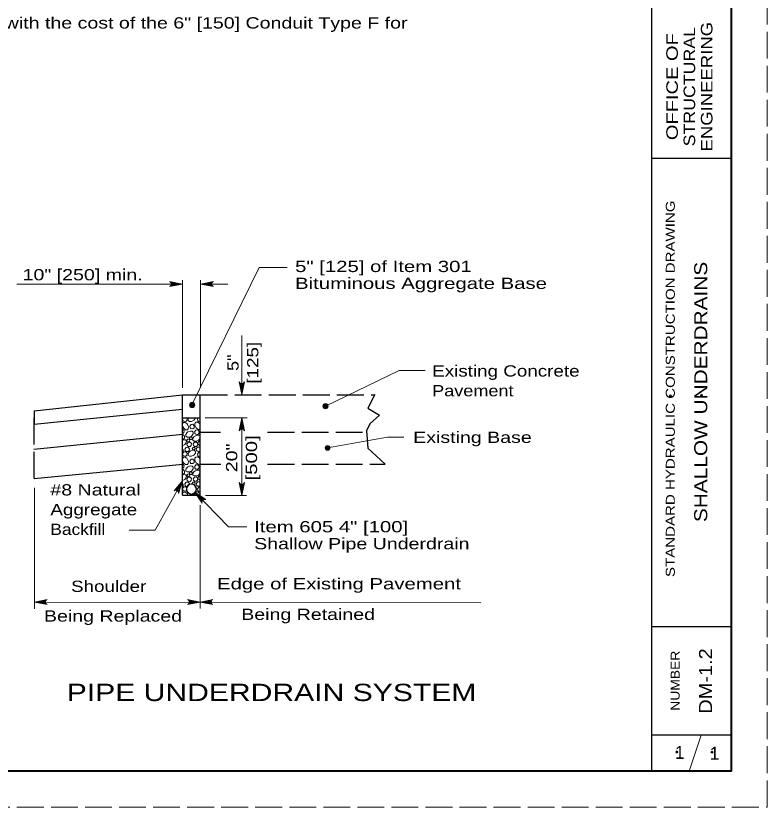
# Model space of a CAD drawing. Extents: x 743.9 to 777.9, y 1051 to 1073.
# Drawn here: x 767.45 to 777.86, y 1051.02 to 1062 of the extents above; entities that cross this region are included whole.
import ezdxf
from ezdxf.enums import TextEntityAlignment as Align

# ---------------------------------------------------------------- set-up
doc = ezdxf.new("R2010")
doc.units = 0
doc.header["$LTSCALE"] = 0.062
doc.header["$PDMODE"] = 32
doc.header["$PDSIZE"] = 0.031
doc.linetypes.add('LONG_DASHED', pattern=[7.5, 6, -1.5])
doc.layers.add('1', color=7, linetype='Continuous', lineweight=13)

msp = doc.modelspace()

# ---------------------------------------------------------------- hatches: boundary and pattern name
at = {"layer": '1'}
for points in [[(769.92886, 1056.59658, 1), (769.85571, 1056.59658, 1)], [(771.77651, 1056.58065, 1), (771.70336, 1056.58065, 1)], [(771.80127, 1056.00261, 1), (771.73603, 1056.00261, 1)]]:
    msp.add_hatch(color=256, dxfattribs=at).paths.add_polyline_path(points)

# ---------------------------------------------------------------- linework, layer by layer
at = {"layer": '1', "lineweight": 25}
for p, q in [((776.26317, 1051.51808), (776.26317, 1072.51808)), ((777.36317, 1072.51808), (777.36317, 1051.51808)), ((777.36317, 1060.01808), (776.26317, 1060.01808)), ((767.70358, 1056.51633), (769.75942, 1056.74008)), ((769.75942, 1055.3475), (769.75942, 1056.74008)), ((769.75942, 1056.74008), (770.00417, 1056.74008)), ((770.00417, 1055.34517), (770.00417, 1056.74008)), ((767.69958, 1056.33075), (769.7575, 1056.53842)), ((767.70358, 1056.51633), (767.70358, 1056.33075)), ((769.75942, 1056.41667), (770.00525, 1056.41667)), ((767.69542, 1055.98542), (769.76075, 1056.19383)), ((767.70358, 1055.57525), (769.76275, 1055.77817)), ((769.75942, 1055.3475), (770.00417, 1055.34517)), ((777.36317, 1053.51808), (776.26317, 1053.51808)), ((777.36317, 1052.01808), (776.26317, 1052.01808))]:
    msp.add_line(p, q, dxfattribs=at)
at = {"layer": '1'}
for p, q in [((769.88458, 1056.58892), (770.8195, 1058.50383)), ((770.8195, 1058.50383), (771.20708, 1058.50383)), ((767.4595, 1058.27442), (769.75608, 1058.27442)), ((769.59392, 1058.24958), (769.75608, 1058.27442)), ((769.59583, 1058.29683), (769.75608, 1058.27442)), ((769.60008, 1058.26), (769.75608, 1058.27442)), ((769.60125, 1058.28575), (769.75608, 1058.27442)), ((769.60292, 1058.27442), (769.75608, 1058.27442)), ((769.75667, 1056.83492), (769.75667, 1058.32867)), ((770.00917, 1056.83492), (770.00917, 1058.32867)), ((770.17008, 1058.29683), (770.00983, 1058.27442)), ((770.16467, 1058.28575), (770.00983, 1058.27442)), ((770.00983, 1058.27442), (770.38867, 1058.27442)), ((770.163, 1058.27442), (770.00983, 1058.27442)), ((770.16583, 1058.26), (770.00983, 1058.27442)), ((770.172, 1058.24958), (770.00983, 1058.27442)), ((770.581, 1056.74008), (770.581, 1057.56217)), ((770.60583, 1056.90242), (770.581, 1056.74033)), ((770.55858, 1056.90058), (770.581, 1056.74033)), ((770.56975, 1056.89517), (770.581, 1056.74033)), ((770.59542, 1056.89633), (770.581, 1056.74033)), ((770.581, 1056.8935), (770.581, 1056.74033)), ((769.75942, 1056.40458), (769.76792, 1056.41667)), ((769.96542, 1056.39983), (769.97717, 1056.41667)), ((770.072, 1056.41667), (770.65317, 1056.41667)), ((770.55617, 1056.2545), (770.581, 1056.41667)), ((770.56658, 1056.26067), (770.581, 1056.41667)), ((770.581, 1056.2635), (770.581, 1056.41667)), ((770.59233, 1056.26183), (770.581, 1056.41667)), ((770.60342, 1056.25642), (770.581, 1056.41667)), ((770.00058, 1056.33142), (770.00242, 1056.327)), ((769.99625, 1056.22383), (770.0025, 1056.23242)), ((771.76867, 1056.00258), (772.59792, 1056.15175)), ((772.59792, 1056.15175), (772.82492, 1056.15175)), ((770.00058, 1055.848), (770.00325, 1055.84117)), ((769.99625, 1055.74042), (770.0035, 1055.75058)), ((769.75942, 1055.54325), (769.3795, 1054.86108)), ((769.66233, 1055.41383), (769.75942, 1055.54325)), ((769.67467, 1055.41325), (769.75942, 1055.54325)), ((769.68533, 1055.40925), (769.75942, 1055.54325)), ((769.69658, 1055.39975), (769.75942, 1055.54325)), ((769.70267, 1055.38933), (769.75942, 1055.54325)), ((770.55858, 1055.50342), (770.581, 1055.34317)), ((770.56967, 1055.498), (770.581, 1055.34317)), ((770.60575, 1055.50533), (770.581, 1055.34317)), ((770.59533, 1055.49917), (770.581, 1055.34317)), ((770.581, 1055.49633), (770.581, 1055.34317)), ((767.70592, 1055.44558), (767.70592, 1053.7715)), ((770.03817, 1055.27675), (769.93125, 1055.38642)), ((770.0505, 1055.28475), (769.93125, 1055.38642)), ((770.06217, 1055.28758), (769.93125, 1055.38642)), ((770.03125, 1055.26767), (769.93125, 1055.38642)), ((770.02708, 1055.256), (769.93125, 1055.38642)), ((769.82858, 1055.36058), (769.83408, 1055.34675)), ((770.00058, 1055.36475), (770.00417, 1055.3555)), ((770.07858, 1055.34342), (770.64308, 1055.34342)), ((770.0035, 1053.77283), (770.0035, 1055.20825)), ((769.01842, 1054.86108), (769.3795, 1054.86108)), ((767.86617, 1053.88558), (767.70592, 1053.86317)), ((767.86075, 1053.8745), (767.70592, 1053.86317)), ((767.70592, 1053.86317), (773.89367, 1053.85258)), ((767.85908, 1053.86317), (767.70592, 1053.86317)), ((767.86192, 1053.84875), (767.70592, 1053.86317)), ((767.86808, 1053.83842), (767.70592, 1053.86317)), ((769.84133, 1053.83842), (770.0035, 1053.86317)), ((769.84325, 1053.88558), (770.0035, 1053.86317)), ((769.8475, 1053.84875), (770.0035, 1053.86317)), ((769.84867, 1053.8745), (770.0035, 1053.86317)), ((769.85033, 1053.86317), (770.0035, 1053.86317)), ((770.16375, 1053.88558), (770.0035, 1053.86317)), ((770.15833, 1053.8745), (770.0035, 1053.86317)), ((770.15667, 1053.86317), (770.0035, 1053.86317)), ((770.1595, 1053.84875), (770.0035, 1053.86317)), ((770.16567, 1053.83842), (770.0035, 1053.86317)), ((776.77983, 1051.51808), (776.9465, 1052.01808))]:
    msp.add_line(p, q, dxfattribs=at)
at = {"layer": '1', "linetype": 'LONG_DASHED', "lineweight": 25}
for p, q in [((770.01133, 1056.74008), (772.42617, 1056.74008)), ((767.70358, 1055.57525), (767.70358, 1056.51633)), ((770.00808, 1056.22125), (770.28617, 1056.22125)), ((770.93842, 1056.22125), (772.31067, 1056.22125)), ((770.003, 1055.77817), (770.28842, 1055.77817)), ((770.93842, 1055.77817), (772.56642, 1055.77817))]:
    msp.add_line(p, q, dxfattribs=at)
at = {"layer": '1', "linetype": 'LONG_DASHED'}
msp.add_lwpolyline([(743.86317, 1051.01808), (777.86317, 1051.01808), (777.86317, 1073.01808), (743.86317, 1073.01808)], close=True, dxfattribs=at)
at = {"layer": '1', "lineweight": 25}
msp.add_lwpolyline([(777.36317, 1051.51808), (745.86317, 1051.51808), (745.86317, 1072.51808)], dxfattribs=at)
at = {"layer": '1', "lineweight": 40}
msp.add_lwpolyline([(745.86317, 1072.51808), (777.36317, 1072.51808), (777.36317, 1051.51808), (745.86317, 1051.51808)], close=True, dxfattribs=at)
msp.add_lwpolyline([(745.86317, 1072.51808), (777.36317, 1072.51808), (777.36317, 1051.51808), (745.86317, 1051.51808)], close=True, dxfattribs=at)
at = {"layer": '1'}
for points in [[(769.57908, 1058.239), (769.75608, 1058.27442), (769.57908, 1058.30983)], [(770.18683, 1058.239), (770.00983, 1058.27442), (770.18683, 1058.30983)], [(771.73992, 1056.58067), (772.7615, 1057.07483), (773.12267, 1057.07483)], [(770.61642, 1056.91733), (770.581, 1056.74033), (770.54567, 1056.91733)], [(769.81658, 1056.41667), (769.82225, 1056.41075), (769.81958, 1056.3835), (769.80283, 1056.36958), (769.77617, 1056.37158), (769.7635, 1056.38367), (769.75942, 1056.40408)], [(769.75942, 1056.33867), (769.7705, 1056.35417), (769.79492, 1056.35592), (769.81675, 1056.34183), (769.82942, 1056.32583)], [(769.93725, 1056.41667), (769.93708, 1056.413), (769.91617, 1056.38608), (769.88375, 1056.36992), (769.85317, 1056.36933), (769.83592, 1056.38158), (769.83433, 1056.40592), (769.84125, 1056.41667)], [(770.0025, 1056.262), (769.9975, 1056.25675), (769.97392, 1056.25725), (769.947, 1056.27817), (769.93083, 1056.31058), (769.93033, 1056.341), (769.9425, 1056.35825), (769.96683, 1056.36), (769.98867, 1056.34608), (770.00133, 1056.32992)], [(770.00225, 1056.36542), (769.982, 1056.36675), (769.9695, 1056.379), (769.96542, 1056.39983)], [(770.54558, 1056.23967), (770.581, 1056.41667), (770.61633, 1056.23967)], [(770.581, 1055.3495), (770.581, 1055.863), (770.581, 1056.41667)], [(769.82858, 1056.32708), (769.84117, 1056.2955), (769.83867, 1056.26642), (769.8255, 1056.25258), (769.80192, 1056.253), (769.77508, 1056.27408), (769.75942, 1056.30525)], [(769.75942, 1056.26217), (769.76167, 1056.26225), (769.7805, 1056.24283), (769.77767, 1056.21558), (769.76108, 1056.20175), (769.75942, 1056.20175)], [(769.859, 1056.30317), (769.876, 1056.32733), (769.90283, 1056.32892), (769.92175, 1056.30933), (769.919, 1056.28208), (769.90225, 1056.26817), (769.87558, 1056.27017), (769.86308, 1056.28225), (769.85908, 1056.30317)], [(769.92667, 1056.22467), (769.94367, 1056.24875), (769.97067, 1056.25042), (769.9895, 1056.23083), (769.98667, 1056.20367), (769.97008, 1056.18983), (769.94342, 1056.19167), (769.93083, 1056.20383), (769.92675, 1056.22467)], [(769.75942, 1056.18258), (769.76917, 1056.18317), (769.78792, 1056.16367), (769.78517, 1056.13633), (769.76858, 1056.12258), (769.75942, 1056.12308)], [(769.83233, 1056.22258), (769.86392, 1056.23517), (769.89317, 1056.23267), (769.90692, 1056.2195), (769.90642, 1056.196), (769.8855, 1056.169), (769.85308, 1056.15283), (769.82242, 1056.15233), (769.80542, 1056.16458), (769.80367, 1056.18883), (769.81775, 1056.21067), (769.83375, 1056.22333)], [(770.00267, 1056.13683), (769.98383, 1056.11242), (769.95142, 1056.09642), (769.92075, 1056.09583), (769.9035, 1056.108), (769.90192, 1056.13225), (769.91583, 1056.15408), (769.93183, 1056.16683)], [(769.93058, 1056.166), (769.96225, 1056.1785), (769.99125, 1056.17617), (770.00258, 1056.16525)], [(770.0025, 1056.20067), (770.00033, 1056.20283), (769.99633, 1056.22383)], [(769.75942, 1056.1105), (769.76867, 1056.11408), (769.79792, 1056.11158), (769.81158, 1056.09842), (769.81117, 1056.07483), (769.79025, 1056.048), (769.75942, 1056.03258)], [(770.00283, 1056.04008), (769.98867, 1056.04108), (769.97608, 1056.05317), (769.972, 1056.07417), (769.98883, 1056.09817), (770.00283, 1056.099)], [(769.75942, 1055.98458), (769.76558, 1055.97875), (769.76508, 1055.95525), (769.75942, 1055.94808)], [(769.75942, 1055.9215), (769.77633, 1055.94533), (769.80342, 1055.947), (769.82225, 1055.9275), (769.81958, 1055.90017), (769.80283, 1055.88633), (769.77617, 1055.88817), (769.7635, 1055.9005), (769.75942, 1055.92083)], [(769.86308, 1055.95633), (769.89458, 1055.96892), (769.92375, 1055.96633), (769.93758, 1055.95317), (769.93708, 1055.92958), (769.91617, 1055.90275), (769.88375, 1055.88658), (769.85317, 1055.88608), (769.83592, 1055.89825), (769.83433, 1055.92258), (769.84842, 1055.94433), (769.86425, 1055.95717)], [(769.894, 1055.99492), (769.90408, 1056.00933), (769.92033, 1056.01025), (769.93167, 1055.99858), (769.93, 1055.98217), (769.92, 1055.97392), (769.90392, 1055.97508), (769.89658, 1055.98233), (769.89408, 1055.99492)], [(769.94933, 1055.98875), (769.96633, 1056.01275), (769.99342, 1056.01425), (770.00292, 1056.00442)], [(770.003, 1055.96225), (769.99283, 1055.95358), (769.96608, 1055.95558), (769.9535, 1055.96775), (769.94942, 1055.98875)], [(770.00317, 1055.88192), (769.982, 1055.8835), (769.9695, 1055.89575), (769.96542, 1055.91658), (769.98233, 1055.94067), (770.003, 1055.94192)], [(769.75942, 1055.85542), (769.7705, 1055.87092), (769.79492, 1055.87267), (769.81675, 1055.85858), (769.82942, 1055.84258)], [(769.82858, 1055.84383), (769.84117, 1055.81217), (769.83867, 1055.78325), (769.8255, 1055.76933), (769.80192, 1055.76967), (769.77508, 1055.79075), (769.75942, 1055.82192)], [(769.859, 1055.81992), (769.876, 1055.844), (769.90283, 1055.84558), (769.92175, 1055.82608), (769.919, 1055.79875), (769.90225, 1055.78492), (769.87558, 1055.78692), (769.86308, 1055.799), (769.85908, 1055.81992)], [(770.00342, 1055.77967), (769.9975, 1055.7735), (769.97392, 1055.774), (769.947, 1055.79483), (769.93083, 1055.82733), (769.93033, 1055.85792), (769.9425, 1055.875), (769.96683, 1055.87675), (769.98867, 1055.86267), (770.00133, 1055.84667)], [(769.75942, 1055.77892), (769.76167, 1055.779), (769.7805, 1055.75942), (769.77767, 1055.73233), (769.76108, 1055.71842), (769.75942, 1055.7185)], [(769.75942, 1055.69933), (769.76917, 1055.69992), (769.78792, 1055.68042), (769.78517, 1055.65308), (769.76858, 1055.63917), (769.75942, 1055.63992)], [(769.83233, 1055.73933), (769.86392, 1055.75175), (769.89317, 1055.74933), (769.90692, 1055.73625), (769.90642, 1055.71258), (769.8855, 1055.68575), (769.85308, 1055.6695), (769.82242, 1055.669), (769.80542, 1055.68133), (769.80367, 1055.70558), (769.81775, 1055.72725), (769.83375, 1055.74008)], [(769.92667, 1055.74142), (769.94367, 1055.76558), (769.97067, 1055.76708), (769.9895, 1055.74758), (769.98667, 1055.72042), (769.97008, 1055.70642), (769.94342, 1055.70842), (769.93083, 1055.72058), (769.92675, 1055.74142)], [(769.93058, 1055.68275), (769.96225, 1055.69525), (769.99125, 1055.69275), (770.00367, 1055.68108)], [(770.00367, 1055.71658), (770.00033, 1055.71958), (769.99633, 1055.74042)], [(769.75942, 1055.62717), (769.76867, 1055.63075), (769.79792, 1055.62833), (769.81158, 1055.61517), (769.81117, 1055.59158), (769.79025, 1055.56475), (769.75942, 1055.5495)], [(770.00367, 1055.65467), (769.98383, 1055.62917), (769.95142, 1055.613), (769.92075, 1055.61258), (769.9035, 1055.62475), (769.90192, 1055.649), (769.91583, 1055.67075), (769.93183, 1055.68358)], [(770.00392, 1055.55675), (769.98867, 1055.55783), (769.97608, 1055.56992), (769.972, 1055.59075), (769.98883, 1055.61492), (770.00367, 1055.61575)], [(769.70483, 1055.37125), (769.75942, 1055.54325), (769.64283, 1055.4055)], [(769.75942, 1055.50133), (769.76558, 1055.4955), (769.76508, 1055.47183), (769.75942, 1055.46467)], [(769.82533, 1055.46733), (769.808, 1055.4685), (769.79542, 1055.48092), (769.79133, 1055.50175), (769.80825, 1055.52583), (769.83533, 1055.52742), (769.85408, 1055.50783), (769.85233, 1055.49108)], [(769.894, 1055.5115), (769.90408, 1055.52608), (769.92033, 1055.527), (769.93167, 1055.51533), (769.93, 1055.49892), (769.92, 1055.49058), (769.91383, 1055.49108)], [(769.89942, 1055.49608), (769.89658, 1055.49908), (769.89408, 1055.5115)], [(769.94933, 1055.50533), (769.96633, 1055.5295), (769.99342, 1055.531), (770.00392, 1055.52)], [(770.004, 1055.47975), (769.99283, 1055.47033), (769.96608, 1055.47233), (769.9535, 1055.48442), (769.94942, 1055.50533)], [(770.61633, 1055.52017), (770.581, 1055.34317), (770.54558, 1055.52017)], [(769.75942, 1055.43808), (769.77633, 1055.46208), (769.80342, 1055.46367), (769.81683, 1055.44975)], [(769.81608, 1055.41408), (769.80283, 1055.403), (769.77617, 1055.40492), (769.7635, 1055.41717), (769.75942, 1055.43758)], [(769.75942, 1055.37217), (769.7705, 1055.38767), (769.79492, 1055.38925), (769.81675, 1055.37533), (769.82942, 1055.35933)], [(769.93083, 1055.34592), (769.93033, 1055.3745), (769.9425, 1055.39175), (769.96683, 1055.39333), (769.98867, 1055.37942), (770.00133, 1055.36342)], [(770.08017, 1055.28433), (769.93125, 1055.38642), (770.0295, 1055.23492)], [(769.93125, 1055.38642), (770.39608, 1054.90908), (770.6485, 1054.90908)], [(770.00417, 1055.39867), (769.982, 1055.40017), (769.9695, 1055.41233), (769.96542, 1055.43342), (769.98233, 1055.45733), (770.004, 1055.45867)], [(769.86592, 1055.34642), (769.876, 1055.36083), (769.90283, 1055.36233), (769.91867, 1055.346)], [(767.88292, 1053.82775), (767.70592, 1053.86317), (767.88292, 1053.89858)], [(769.8265, 1053.82775), (770.0035, 1053.86317), (769.8265, 1053.89858)], [(770.1805, 1053.82775), (770.0035, 1053.86317), (770.1805, 1053.89858)]]:
    msp.add_lwpolyline(points, dxfattribs=at)
at = {"layer": '1', "linetype": 'LONG_DASHED', "lineweight": 25}
msp.add_lwpolyline([(772.42658, 1056.741), (772.3255, 1056.55217), (772.48975, 1056.45617), (772.35675, 1056.33617), (772.30983, 1056.24017), (772.3255, 1056.00008), (772.56683, 1055.77817)], dxfattribs=at)
msp.add_lwpolyline([(772.42658, 1056.741), (772.3255, 1056.55217), (772.48975, 1056.45617), (772.35675, 1056.33617), (772.30983, 1056.24017), (772.3255, 1056.00008), (772.56683, 1055.77817)], dxfattribs=at)
msp.add_lwpolyline([(772.42658, 1056.741), (772.3255, 1056.55217), (772.48975, 1056.45617), (772.35675, 1056.33617), (772.30983, 1056.24017), (772.3255, 1056.00008), (772.56683, 1055.77817)], dxfattribs=at)
at = {"layer": '1'}
for points in [[(769.85508, 1056.13783), (769.86525, 1056.15225), (769.88142, 1056.15308), (769.89283, 1056.14142), (769.89117, 1056.12517), (769.88117, 1056.11675), (769.86508, 1056.118), (769.8575, 1056.12517)], [(769.81908, 1056.0555), (769.83592, 1056.0795), (769.86308, 1056.08117), (769.88183, 1056.06158), (769.879, 1056.03433), (769.86242, 1056.0205), (769.83558, 1056.02242), (769.82317, 1056.03458)], [(769.82008, 1056.10842), (769.83025, 1056.12275), (769.8465, 1056.12367), (769.85792, 1056.11208), (769.85625, 1056.09583), (769.84617, 1056.08742), (769.83017, 1056.08858), (769.82267, 1056.09592)], [(769.90642, 1056.0565), (769.92333, 1056.08067), (769.95042, 1056.08225), (769.969, 1056.06267), (769.96633, 1056.03533), (769.94967, 1056.0215), (769.92292, 1056.02342), (769.9105, 1056.03558)], [(769.79133, 1055.98492), (769.80825, 1056.00908), (769.83533, 1056.01067), (769.85408, 1055.99108), (769.85125, 1055.96383), (769.83475, 1055.95), (769.808, 1055.95192), (769.79542, 1055.96408)], [(769.81908, 1055.57225), (769.83592, 1055.59633), (769.86308, 1055.59775), (769.88183, 1055.57833), (769.879, 1055.55117), (769.86242, 1055.53717), (769.83558, 1055.53917), (769.82317, 1055.55133)], [(769.82008, 1055.62508), (769.83025, 1055.6395), (769.8465, 1055.6405), (769.85792, 1055.62875), (769.85625, 1055.61242), (769.84617, 1055.60408), (769.83017, 1055.60525), (769.82267, 1055.61258)], [(769.85508, 1055.65442), (769.86525, 1055.669), (769.88142, 1055.66983), (769.89283, 1055.65817), (769.89117, 1055.64175), (769.88117, 1055.63342), (769.86508, 1055.63458), (769.8575, 1055.64192)], [(769.90642, 1055.57325), (769.92333, 1055.59725), (769.95042, 1055.59883), (769.969, 1055.57942), (769.96633, 1055.55208), (769.94967, 1055.53817), (769.92292, 1055.54017), (769.9105, 1055.55233)]]:
    msp.add_lwpolyline(points, close=True, dxfattribs=at)
for centre, radius in [((769.89228, 1056.59658), 0.03658), ((771.73994, 1056.58065), 0.03658), ((771.76865, 1056.00261), 0.03262)]:
    msp.add_circle(centre, radius, dxfattribs=at)
for centre, radius, start, end in [((769.56478, 1058.27444), 0.0382, 292.08605, 67.91218), ((770.20115, 1058.27444), 0.0382, 112.08782, 247.91395), ((770.581, 1056.93162), 0.0382, 202.08782, 337.91395), ((770.58101, 1056.22534), 0.0382, 22.08782, 157.91395), ((770.58094, 1055.53446), 0.0382, 202.08782, 337.91395), ((769.66687, 1055.37586), 0.0382, 353.14887, 128.975), ((769.88068, 1055.4302), 0.068, 180, 0), ((770.06479, 1055.2494), 0.0382, 66.36011, 202.18623), ((767.89724, 1053.86321), 0.0382, 112.08782, 247.91395), ((769.81221, 1053.86321), 0.0382, 292.08605, 67.91218), ((770.1948, 1053.86321), 0.0382, 112.08782, 247.91395)]:
    msp.add_arc(centre, radius, start, end, dxfattribs=at)
at = {"layer": '1', "lineweight": 25}
for centre, start, end in [((769.88228, 1055.4302), 0, 180), ((769.88304, 1055.4302), 0, 180), ((769.88228, 1055.4302), 180, 0)]:
    msp.add_arc(centre, 0.068, start, end, dxfattribs=at)
at = {"layer": '1'}
for p in [(776.52058, 1056.72408), (776.95342, 1056.73142), (776.61125, 1051.78183), (777.09967, 1051.78083)]:
    msp.add_point(p, dxfattribs=at)

# ---------------------------------------------------------------- texts
for s, width, p in [('shall be included with the cost of the 6" [150] Conduit Type F for ', 1.3, (765.1985, 1061.8195)), ('5" [125] of Item 301', 1.35, (771.319, 1058.44125)), ('10" [250] min.', 1.3, (767.54117, 1058.32625)), ('Bituminous Aggregate Base', 1.35, (771.319, 1058.20658)), ('Existing Concrete', 1.25, (773.21942, 1056.9915)), ('Pavement', 1.2, (773.21942, 1056.7175)), ('Existing Base', 1.3, (772.95658, 1056.07075)), ('#8 Natural', 1.3, (767.9265, 1055.34208)), ('Aggregate', 1.25, (767.9265, 1055.06808)), ('Backfill', 1.15, (767.9265, 1054.79408)), ('Item 605 4" [100]', 1.35, (770.7515, 1054.83042)), ('Shallow Pipe Underdrain', 1.3, (770.7515, 1054.59575)), ('Edge of Existing Pavement', 1.35, (770.23692, 1054.03908)), ('Being Retained', 1.3, (770.57233, 1053.61533))]:
    msp.add_text(s, height=0.156, dxfattribs=dict(at, width=width)).set_placement(p)
for s, height, width, p in [('ENGINEERING', 0.16, 1.2, (777.10492, 1061.01263)), ('OFFICE OF', 0.16, 1.3, (776.62492, 1061.01254)), ('STRUCTURAL', 0.16, 1.15, (776.86492, 1061.01254)), ('STANDARD HYDRAULIC CONSTRUCTION DRAWING', 0.125, 1.25, (776.58308, 1056.82212)), ('SHALLOW UNDERDRAINS', 0.18, 1.2, (777.032, 1056.77817)), ('[125]', 0.156, 1.25, (770.80983, 1057.183)), ('5"', 0.156, 1.2, (770.53583, 1057.18304)), ('[500]', 0.156, 1.35, (770.79158, 1055.86333)), ('20"', 0.156, 1.3, (770.51758, 1055.86333)), ('NUMBER', 0.125, 1.15, (776.65017, 1052.77217)), ('DM-1.2', 0.18, 1.15, (777.0985, 1052.76846))]:
    msp.add_text(s, height=height, rotation=90, dxfattribs=dict(at, width=width)).set_placement(p, align=Align.CENTER)
for s, height, width, p in [('Shoulder', 0.156, 1.25, (768.73475, 1054.00408)), ('Being Replaced', 0.156, 1.3, (768.79492, 1053.59225)), ('PIPE UNDERDRAIN SYSTEM', 0.24, 1.3, (770.99279, 1052.49017))]:
    msp.add_text(s, height=height, dxfattribs=dict(at, width=width)).set_placement(p, align=Align.CENTER)
for p in [(776.65102, 1051.68817), (777.13385, 1051.67558)]:
    msp.add_text('1', height=0.18, dxfattribs=at).set_placement(p, align=Align.CENTER)

doc.saveas('drawing.dxf')
